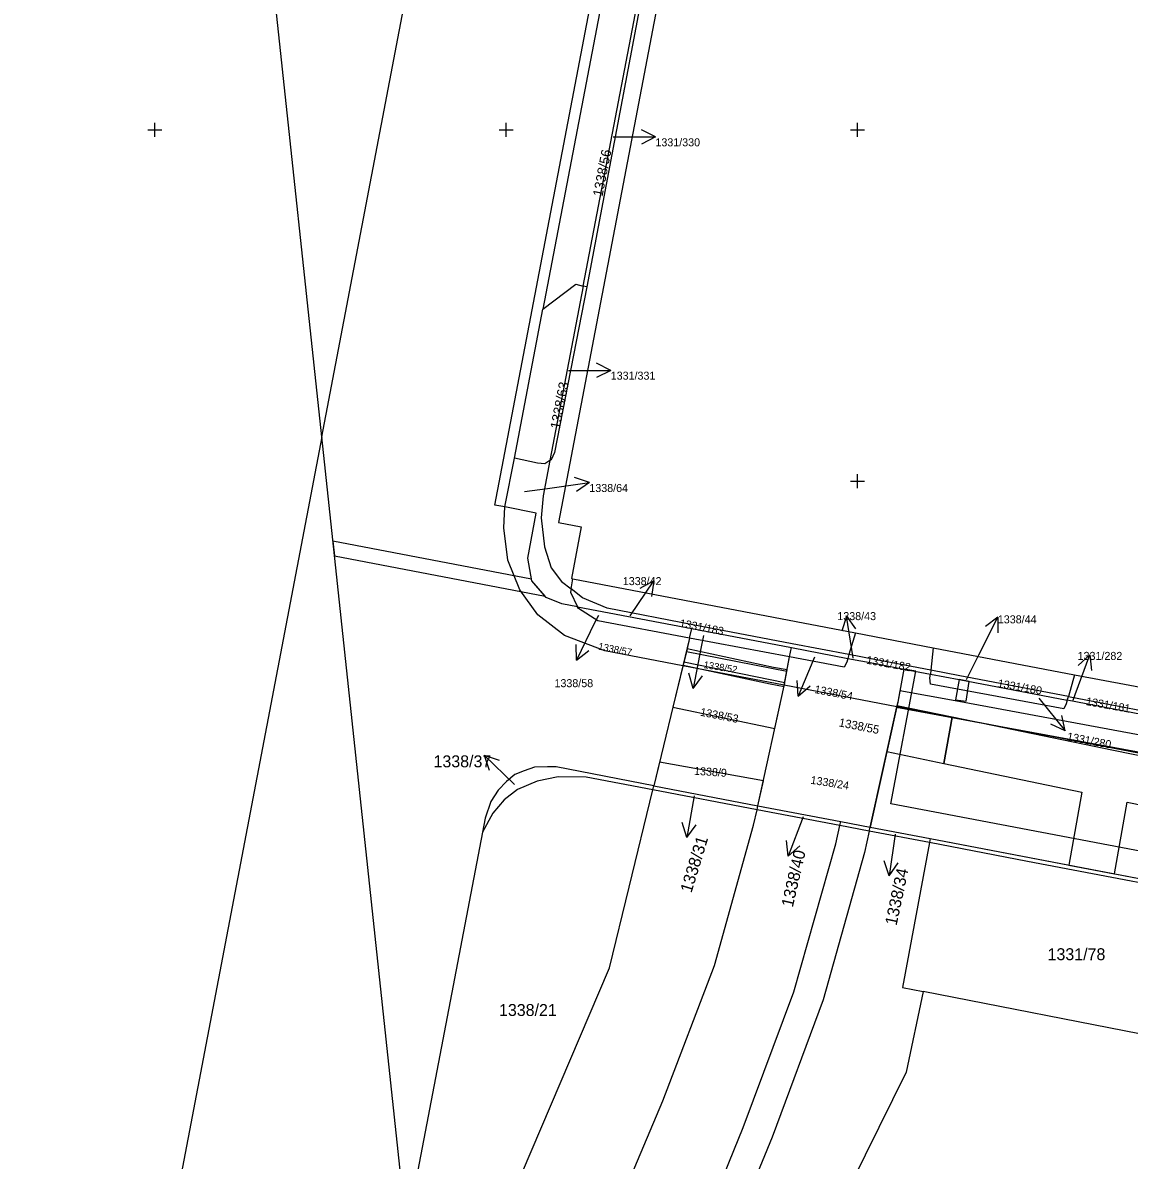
# Model space of a CAD drawing. Extents: x -601602 to -600882, y -1162594 to -1161950.
# Drawn here: x -601309.4 to -601230.7, y -1162198.3 to -1162117.4 of the extents above; entities that cross this region are included whole.
import ezdxf

# ---------------------------------------------------------------- set-up
doc = ezdxf.new("R2010")
doc.units = 0
for name, color, linetype in [('KN_Hranice parcel', 7, 'Continuous'), ('KN_Parcelní čísla', 7, 'Continuous'), ('KN_Pop  PČ popisy', 7, 'Continuous'), ('KN_Vnitřní kresba', 7, 'Continuous'), ('KN_Věcná břemena k části', 7, 'Continuous'), ('X_SOUR_KRIZKY_SEVER', 7, 'Continuous')]:
    doc.layers.add(name, color=color, linetype=linetype)

# ---------------------------------------------------------------- blocks, each defined once
blk = doc.blocks.new('1029_31')
at = {"layer": 'KN_Pop  PČ popisy'}
for p, q in [((0, 0), (1.362, 2.674)), ((1.362, 2.674), (0.462, 2.009)), ((1.362, 2.674), (1.354, 1.554))]:
    blk.add_line(p, q, dxfattribs=at)
blk = doc.blocks.new('1029_32')
at = {"layer": 'KN_Pop  PČ popisy'}
for p, q in [((-0.469, 2.964), (-0.807, 1.897)), ((0, 0), (-0.469, 2.964)), ((-0.469, 2.964), (0.182, 2.053))]:
    blk.add_line(p, q, dxfattribs=at)
blk = doc.blocks.new('1029_33')
at = {"layer": 'KN_Pop  PČ popisy'}
for p, q in [((0, 0), (1.678, 2.488)), ((1.678, 2.488), (0.703, 1.938)), ((1.678, 2.488), (1.533, 1.378))]:
    blk.add_line(p, q, dxfattribs=at)
blk = doc.blocks.new('1029_36')
at = {"layer": 'KN_Pop  PČ popisy'}
for p, q in [((0, 0), (-2.159, 2.085)), ((-2.159, 2.085), (-1.09, 1.749)), ((-2.159, 2.085), (-1.786, 1.029))]:
    blk.add_line(p, q, dxfattribs=at)
blk = doc.blocks.new('1029_37')
at = {"layer": 'KN_Pop  PČ popisy'}
for p, q in [((0, 0), (-0.521, -2.955)), ((-0.521, -2.955), (-0.84, -1.882)), ((-0.521, -2.955), (0.146, -2.056))]:
    blk.add_line(p, q, dxfattribs=at)
blk = doc.blocks.new('1029_38')
at = {"layer": 'KN_Pop  PČ popisy'}
for p, q in [((0, 0), (-1.075, -2.802)), ((-1.075, -2.802), (-1.184, -1.687)), ((-1.075, -2.802), (-0.249, -2.046))]:
    blk.add_line(p, q, dxfattribs=at)
blk = doc.blocks.new('1029_39')
at = {"layer": 'KN_Pop  PČ popisy'}
for p, q in [((0, 0), (-0.418, -2.972)), ((-0.418, -2.972), (-0.774, -1.91)), ((-0.418, -2.972), (0.218, -2.05))]:
    blk.add_line(p, q, dxfattribs=at)
blk = doc.blocks.new('1029_62')
at = {"layer": 'KN_Pop  PČ popisy'}
for p, q in [((0, 0), (3.001, 0)), ((3.001, 0), (2, 0.501)), ((3.001, 0), (2, -0.501))]:
    blk.add_line(p, q, dxfattribs=at)
blk = doc.blocks.new('1029_63')
at = {"layer": 'KN_Pop  PČ popisy'}
for p, q in [((0, 0), (2.972, 0.418)), ((2.972, 0.418), (1.91, 0.774)), ((2.972, 0.418), (2.05, -0.218))]:
    blk.add_line(p, q, dxfattribs=at)
blk = doc.blocks.new('1029_53')
at = {"layer": 'KN_Pop  PČ popisy'}
for p, q in [((0, 0), (-1.316, -2.697)), ((-1.316, -2.697), (-1.327, -1.578)), ((-1.316, -2.697), (-0.426, -2.017))]:
    blk.add_line(p, q, dxfattribs=at)
blk = doc.blocks.new('1029_68')
at = {"layer": 'KN_Pop  PČ popisy'}
for p, q in [((0, 0), (-0.573, -2.946)), ((-0.573, -2.946), (-0.873, -1.867)), ((-0.573, -2.946), (0.11, -2.058))]:
    blk.add_line(p, q, dxfattribs=at)
blk = doc.blocks.new('1029_69')
at = {"layer": 'KN_Pop  PČ popisy'}
for p, q in [((0, 0), (-1.173, -2.762)), ((-1.173, -2.762), (-1.242, -1.645)), ((-1.173, -2.762), (-0.32, -2.036))]:
    blk.add_line(p, q, dxfattribs=at)
blk = doc.blocks.new('1029_70')
at = {"layer": 'KN_Pop  PČ popisy'}
for p, q in [((0, 0), (1.026, 2.82)), ((1.026, 2.82), (0.213, 2.05)), ((1.026, 2.82), (1.154, 1.708))]:
    blk.add_line(p, q, dxfattribs=at)
blk = doc.blocks.new('1029_71')
at = {"layer": 'KN_Pop  PČ popisy'}
for p, q in [((0, 0), (1.889, -2.332)), ((1.889, -2.332), (1.647, -1.239)), ((1.889, -2.332), (0.869, -1.869))]:
    blk.add_line(p, q, dxfattribs=at)

msp = doc.modelspace()

# ---------------------------------------------------------------- linework, layer by layer
at = {"layer": 'KN_Hranice parcel'}
for p, q in [((-601288.12, -1162146.84), (-601297.76, -1162056.59)), ((-601267.25, -1162110.88), (-601272.39, -1162137.77)), ((-601269.51, -1162136.12), (-601265.2, -1162113.58)), ((-601264.99, -1162113.61), (-601269.27, -1162136.18)), ((-601269.51, -1162136.12), (-601271.88, -1162148.52)), ((-601269.27, -1162136.18), (-601269.51, -1162136.12)), ((-601274.41, -1162148.35), (-601272.39, -1162137.77)), ((-601282.09, -1162203.26), (-601288.12, -1162146.84)), ((-601275.1, -1162151.83), (-601274.41, -1162148.35)), ((-601270.38, -1162157.66), (-601270.25, -1162156.94)), ((-601270.25, -1162156.94), (-601250.15, -1162160.78)), ((-601269.92, -1162158.93), (-601261.78, -1162160.48)), ((-601261.95, -1162161.16), (-601261.78, -1162160.48)), ((-601261.78, -1162160.48), (-601254.7, -1162161.83)), ((-601261.95, -1162161.16), (-601262.42, -1162163.13)), ((-601254.83, -1162162.5), (-601261.95, -1162161.16)), ((-601250.15, -1162160.78), (-601250.61, -1162162.33)), ((-601250.15, -1162160.78), (-601244.61, -1162161.84)), ((-601254.83, -1162162.5), (-601254.7, -1162161.83)), ((-601254.7, -1162161.83), (-601250.69, -1162162.6)), ((-601250.61, -1162162.33), (-601250.69, -1162162.6)), ((-601244.61, -1162161.84), (-601244.79, -1162163.45)), ((-601244.61, -1162161.84), (-601234.56, -1162163.76)), ((-601262.42, -1162163.13), (-601264.5, -1162171.67)), ((-601255.21, -1162164.51), (-601262.42, -1162163.13)), ((-601255.21, -1162164.51), (-601254.83, -1162162.5)), ((-601246.7, -1162163.36), (-601244.82, -1162163.72)), ((-601244.79, -1162163.45), (-601244.82, -1162163.72)), ((-601234.56, -1162163.76), (-601235, -1162165.32)), ((-601234.56, -1162163.76), (-601228.86, -1162164.84)), ((-601247.21, -1162166.04), (-601255.21, -1162164.51)), ((-601235.08, -1162165.58), (-601235, -1162165.32)), ((-601229.06, -1162166.73), (-601235.08, -1162165.58)), ((-601235, -1162165.32), (-601229.07, -1162166.45)), ((-601249.11, -1162174.61), (-601247.21, -1162166.04)), ((-601264.57, -1162171.96), (-601264.5, -1162171.67)), ((-601257.15, -1162173.37), (-601264.57, -1162171.96)), ((-601264.5, -1162171.67), (-601257.09, -1162173.09)), ((-601257.15, -1162173.37), (-601257.09, -1162173.09)), ((-601276.69, -1162174.96), (-601282.09, -1162203.26)), ((-601249.17, -1162174.89), (-601249.11, -1162174.61)), ((-601244.89, -1162175.71), (-601249.17, -1162174.89)), ((-601249.11, -1162174.61), (-601244.84, -1162175.42)), ((-601244.84, -1162175.42), (-601244.89, -1162175.71)), ((-601244.84, -1162175.42), (-601200.33, -1162183.92)), ((-601224.66, -1162190.35), (-601245.33, -1162186.3))]:
    msp.add_line(p, q, dxfattribs=at)
for points in [[(-601288.12, -1162146.84), (-601275.21, -1162079.21), (-601276.71, -1162078.25), (-601277.63, -1162077.88), (-601278.53, -1162077.52), (-601279.72, -1162077.24)], [(-601275.1, -1162151.83), (-601275.81, -1162151.7), (-601264.48, -1162092.37), (-601263.76, -1162089.98), (-601262.32, -1162087.45), (-601260.32, -1162085.35), (-601258.15, -1162083.75), (-601255.36, -1162082.92), (-601253.9, -1162082.58), (-601251.36, -1162082.69), (-601243.84, -1162084.09)], [(-601200.05, -1162101.62), (-601200.02, -1162101.45), (-601257.65, -1162090.43), (-601258.35, -1162094.11), (-601259.98, -1162093.8), (-601271.27, -1162152.93), (-601269.66, -1162153.24), (-601270.36, -1162156.92), (-601270.25, -1162156.94)], [(-601272.39, -1162137.77), (-601270.05, -1162135.99), (-601269.51, -1162136.12)], [(-601269.27, -1162136.18), (-601271.57, -1162147.96), (-601271.8, -1162148.47), (-601271.88, -1162148.52)], [(-601288.12, -1162146.84), (-601299.4, -1162206.01), (-601309.39, -1162258.31)], [(-601271.88, -1162148.52), (-601272.25, -1162148.75), (-601272.78, -1162148.71), (-601274.41, -1162148.35)], [(-601271.88, -1162148.52), (-601272.36, -1162151.04), (-601272.51, -1162152.6), (-601272.28, -1162154.67), (-601271.8, -1162156.16), (-601271.07, -1162157.12), (-601270.38, -1162157.66)], [(-601262.42, -1162163.13), (-601267.97, -1162162.07), (-601270.84, -1162160.97), (-601272.74, -1162159.5), (-601274.03, -1162157.73), (-601274.87, -1162155.61), (-601275.16, -1162153.32), (-601275.1, -1162151.83)], [(-601269.92, -1162158.93), (-601271.04, -1162158.72), (-601272.15, -1162158.26), (-601273.17, -1162157.08), (-601273.46, -1162155.46), (-601272.86, -1162152.26), (-601275.1, -1162151.83)], [(-601270.38, -1162157.66), (-601270.42, -1162157.89), (-601269.92, -1162158.93)], [(-601250.61, -1162162.33), (-601254.65, -1162161.56), (-601261.71, -1162160.21), (-601267.82, -1162159.04), (-601269.57, -1162158.29), (-601270.38, -1162157.66)], [(-601261.95, -1162161.16), (-601268.47, -1162159.93), (-601269.86, -1162159.06), (-601269.92, -1162158.93)], [(-601244.79, -1162163.45), (-601246.65, -1162163.09), (-601248.79, -1162162.68), (-601250.61, -1162162.33)], [(-601250.69, -1162162.6), (-601250.77, -1162162.88), (-601250.95, -1162163.23), (-601254.83, -1162162.5)], [(-601250.69, -1162162.6), (-601248.84, -1162162.95), (-601246.7, -1162163.36)], [(-601246.7, -1162163.36), (-601247.14, -1162165.72), (-601247.21, -1162166.04)], [(-601235.08, -1162165.58), (-601235.15, -1162165.84), (-601235.32, -1162166.2), (-601242.9, -1162164.8), (-601244.82, -1162164.44), (-601244.85, -1162163.99), (-601244.82, -1162163.72)], [(-601244.82, -1162163.72), (-601242.77, -1162164.11), (-601235.08, -1162165.58)], [(-601235, -1162165.32), (-601242.72, -1162163.84), (-601244.79, -1162163.45)], [(-601257.09, -1162173.09), (-601255.22, -1162164.56), (-601255.21, -1162164.51)], [(-601205.45, -1162171.24), (-601205.97, -1162173.94), (-601243.26, -1162166.8), (-601247.21, -1162166.04)], [(-601264.5, -1162171.67), (-601271.45, -1162170.32), (-601272.05, -1162170.31), (-601272.98, -1162170.33), (-601273.71, -1162170.61), (-601274.37, -1162170.87), (-601274.97, -1162171.36), (-601275.57, -1162171.97), (-601276.09, -1162172.77), (-601276.5, -1162173.96), (-601276.69, -1162174.96)], [(-601264.57, -1162171.96), (-601269.31, -1162171.06), (-601271.31, -1162171.03), (-601272.79, -1162171.34), (-601274.18, -1162171.92), (-601275.15, -1162172.67), (-601275.94, -1162173.6), (-601276.69, -1162174.96)], [(-601280.79, -1162215.42), (-601267.64, -1162184.62), (-601266.25, -1162178.87), (-601264.57, -1162171.96)], [(-601289.86, -1162251.33), (-601279.49, -1162229.65), (-601276.15, -1162222.45), (-601271.45, -1162212.04), (-601263.86, -1162194.07), (-601260.18, -1162184.46), (-601257.39, -1162174.47), (-601257.15, -1162173.37)], [(-601249.17, -1162174.89), (-601251.26, -1162174.5), (-601257.15, -1162173.37)], [(-601257.09, -1162173.09), (-601251.2, -1162174.21), (-601249.11, -1162174.61)], [(-601249.17, -1162174.89), (-601249.51, -1162176.4), (-601252.45, -1162186.9), (-601256.07, -1162196.65), (-601258.2, -1162201.85), (-601263.81, -1162214.98), (-601268.55, -1162225.42), (-601272.29, -1162233.43), (-601281.21, -1162252.98)], [(-601244.89, -1162175.71), (-601246.79, -1162186.02), (-601245.33, -1162186.3)], [(-601222.67, -1162179.95), (-601237.9, -1162177.04), (-601244.89, -1162175.71)], [(-601245.33, -1162186.3), (-601246.54, -1162192.03), (-601264.07, -1162227.52), (-601276.32, -1162253.92)]]:
    msp.add_lwpolyline(points, dxfattribs=at)
at = {"layer": 'KN_Pop  PČ popisy'}
for p, q in [((-601273.69, -1162150.74), (-601272.05, -1162150.51)), ((-601268.44, -1162159.54), (-601268.68, -1162160.03)), ((-601260.97, -1162160.98), (-601261.13, -1162161.79)), ((-601242.26, -1162164.1), (-601241.37, -1162162.34)), ((-601250.32, -1162162.58), (-601250.32, -1162162.56)), ((-601234.66, -1162165.57), (-601234.51, -1162165.16))]:
    msp.add_line(p, q, dxfattribs=at)
at = {"layer": 'KN_Vnitřní kresba'}
for p, q in [((-601251.54, -1162175.79), (-601251.26, -1162174.5)), ((-601251.26, -1162174.5), (-601251.2, -1162174.21)), ((-601254.54, -1162186.32), (-601251.54, -1162175.79)), ((-601258.13, -1162195.97), (-601254.54, -1162186.32)), ((-601260.19, -1162201.02), (-601258.13, -1162195.97))]:
    msp.add_line(p, q, dxfattribs=at)
at = {"layer": 'KN_Věcná břemena k části'}
for points in [[(-601287.33, -1162154.26), (-601287.22, -1162155.3), (-601272.23, -1162158.17), (-601273.17, -1162157.08), (-601273.19, -1162156.97)], [(-601255.02, -1162163.5), (-601254.83, -1162162.5), (-601261.95, -1162161.16), (-601262.18, -1162162.11)], [(-601255.22, -1162164.56), (-601255, -1162163.42), (-601255.98, -1162163.24), (-601262.13, -1162161.91), (-601262.41, -1162163.08), (-601256.22, -1162164.42), (-601255.23, -1162164.6)], [(-601262.36, -1162162.86), (-601263.14, -1162166.08), (-601255.88, -1162167.58), (-601255.22, -1162164.56), (-601255.18, -1162164.34)], [(-601242.27, -1162165.65), (-601242.07, -1162164.24), (-601242.77, -1162164.11), (-601243.03, -1162165.54)], [(-601247.2, -1162165.98), (-601247.92, -1162169.23), (-601243.86, -1162170.07), (-601243.26, -1162166.79)], [(-601256.7, -1162171.3), (-601264.09, -1162169.98), (-601264.5, -1162171.67), (-601257.09, -1162173.09)]]:
    msp.add_lwpolyline(points, close=True, dxfattribs=at)
for points in [[(-601110.9, -1162199.12), (-601136.18, -1162194.12), (-601244.5, -1162173.54), (-601247.63, -1162172.94), (-601245.85, -1162163.52), (-601246.7, -1162163.36), (-601247.14, -1162165.72), (-601249.11, -1162174.61), (-601244.84, -1162175.42), (-601200.33, -1162183.92), (-601201.03, -1162185.05), (-601136.8, -1162197.26), (-601122.85, -1162200.02)], [(-601226.58, -1162168.67), (-601243.05, -1162165.63), (-601246.99, -1162164.9), (-601247.14, -1162165.72), (-601247.22, -1162166.08), (-601243.26, -1162166.81), (-601226.8, -1162169.85)], [(-601064.31, -1162200.86), (-601081.08, -1162197.65), (-601109.56, -1162192.2), (-601128.66, -1162188.54), (-601200.82, -1162175.41), (-601199.01, -1162172.46), (-601202.48, -1162171.8), (-601204.29, -1162174.75), (-601231.79, -1162169.15), (-601243.26, -1162166.79), (-601243.86, -1162170.07), (-601234.04, -1162172.11), (-601234.97, -1162177.31), (-601231.73, -1162177.92), (-601230.82, -1162172.83), (-601203.86, -1162178.32), (-601130.82, -1162191.5), (-601132.08, -1162200.52)]]:
    msp.add_lwpolyline(points, dxfattribs=at)
at = {"layer": 'X_SOUR_KRIZKY_SEVER'}
for p, q in [((-601300.5, -1162125), (-601299.5, -1162125)), ((-601300, -1162125.5), (-601300, -1162124.5)), ((-601275.5, -1162125), (-601274.5, -1162125)), ((-601275, -1162125.5), (-601275, -1162124.5)), ((-601250.5, -1162125), (-601249.5, -1162125)), ((-601250, -1162125.5), (-601250, -1162124.5)), ((-601250.5, -1162150), (-601249.5, -1162150)), ((-601250, -1162150.5), (-601250, -1162149.5))]:
    msp.add_line(p, q, dxfattribs=at)

# ---------------------------------------------------------------- block references
at = {"layer": 'KN_Pop  PČ popisy'}
for name, p in [('1029_62', (-601267.38, -1162125.51)), ('1029_62', (-601270.56, -1162142.11)), ('1029_63', (-601272.05, -1162150.51)), ('1029_33', (-601266.18, -1162159.57)), ('1029_32', (-601250.32, -1162162.56)), ('1029_31', (-601241.37, -1162162.34)), ('1029_53', (-601268.68, -1162160.03)), ('1029_68', (-601261.13, -1162161.79)), ('1029_70', (-601234.51, -1162165.16)), ('1029_69', (-601253.06, -1162162.52)), ('1029_71', (-601237.11, -1162165.42)), ('1029_36', (-601274.41, -1162171.58)), ('1029_37', (-601261.63, -1162172.39)), ('1029_38', (-601253.86, -1162173.88)), ('1029_39', (-601247.33, -1162175.1))]:
    msp.add_blockref(name, p, dxfattribs=at)

# ---------------------------------------------------------------- texts
at = {"layer": 'KN_Parcelní čísla'}
for s, height, p in [('1331/330', 0.5695, (-601264.38, -1162126.174)), ('1331/331', 0.5695, (-601267.56, -1162142.774)), ('1338/64', 0.5695, (-601269.08, -1162150.764)), ('1338/42', 0.5695, (-601266.7, -1162157.389)), ('1338/43', 0.5695, (-601251.437, -1162159.879)), ('1338/44', 0.5695, (-601240.019, -1162160.109)), ('1331/282', 0.5695, (-601234.342, -1162162.709)), ('1338/58', 0.5695, (-601271.561, -1162164.649)), ('1338/37', 0.85, (-601280.166, -1162170.35)), ('1331/78', 0.85, (-601236.479, -1162184.07)), ('1338/21', 0.85, (-601275.507, -1162188.04))]:
    msp.add_text(s, height=height, dxfattribs=at).set_placement(p)
for s, height, rotation, p in [('1338/56', 0.7, 79, (-601268.152, -1162129.793)), ('1338/63', 0.7, 79, (-601271.182, -1162146.333)), ('1331/183', 0.5695, 349, (-601262.699, -1162160.354)), ('1338/57', 0.5, 349, (-601268.475, -1162161.97)), ('1338/52', 0.5, 351, (-601260.978, -1162163.283)), ('1331/182', 0.5695, 350, (-601249.403, -1162162.973)), ('1338/54', 0.5695, 349, (-601253.098, -1162165.059)), ('1331/180', 0.5695, 350, (-601240.064, -1162164.638)), ('1331/181', 0.5695, 350, (-601233.781, -1162165.916)), ('1338/53', 0.5695, 349, (-601261.233, -1162166.67)), ('1338/55', 0.6, 349, (-601251.367, -1162167.431)), ('1331/280', 0.5695, 349, (-601235.133, -1162168.414)), ('1338/9', 0.5695, 356, (-601261.644, -1162170.874)), ('1338/24', 0.5695, 351, (-601253.374, -1162171.514)), ('1338/31', 0.85, 73, (-601261.82, -1162179.331)), ('1338/40', 0.85, 77, (-601254.608, -1162180.351)), ('1338/34', 0.85, 78, (-601247.227, -1162181.65))]:
    msp.add_text(s, height=height, rotation=rotation, dxfattribs=at).set_placement(p)

doc.saveas('drawing.dxf')
